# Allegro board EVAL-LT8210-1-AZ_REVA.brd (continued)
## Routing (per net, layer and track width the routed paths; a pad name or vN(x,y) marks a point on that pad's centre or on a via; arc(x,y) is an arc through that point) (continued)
UNNAMED_3_DIOLED_I1_P: length 1.5
  TOP w0.762: RPWGD3.1 DS3.A
UNNAMED_3_IND_I87_N1:
  vias: v2(103.76,249.81) v2(103.76,248.67) v2(103.76,247.52) v2(103.76,246.38) v2(103.76,245.24) v2(103.76,244.09) v2(103.76,242.95) v2(103.76,241.81) v2(103.76,240.79) v2(103.76,239.78) v2(104.9,249.81) v2(104.9,248.67) v2(104.9,247.52) v2(106.04,249.81) v2(106.04,248.67) v2(106.04,247.52) v2(106.02,242.93) v2(107.19,248.67) v2(107.19,247.52) v2(108.33,247.52) v2(108.33,246.38) v2(108.33,245.24) v2(108.33,244.09) v2(108.33,242.95) v2(108.33,241.81) v2(108.33,240.79) v2(108.33,239.78) v2(111.76,249.81) v2(111.76,248.67) v2(111.76,247.52) v2(111.76,246.38) v2(111.76,245.24) v2(111.76,244.09) v2(112.9,249.81) v2(112.9,248.67) v2(112.9,247.52) v2(112.9,246.38) v2(112.9,245.24) v2(112.9,244.09) v2(114.05,249.81) v2(114.05,248.67) v2(114.05,247.52) v2(114.05,246.38) v2(114.05,245.24) v2(114.05,244.09) v2(115.19,249.81) v2(115.19,248.67) v2(115.19,247.52) v2(115.19,246.38) v2(115.19,245.24) v2(115.19,244.09) v2(116.33,249.81) v2(116.33,248.67) v2(116.33,247.52) v2(116.33,246.38) v2(116.33,245.24) v2(116.33,244.09) v2(117.35,240.15) v2(117.47,249.81) v2(117.47,248.67) v2(117.47,247.52) v2(117.47,246.38) v2(117.47,245.24) v2(117.47,244.09) v2(118.62,249.81) v2(118.62,248.67) v2(118.62,247.52) v2(118.62,246.38) v2(118.62,245.24) v2(118.62,244.09) v2(119.76,249.81) v2(119.76,248.67) v2(119.76,247.52) v2(119.76,246.38) v2(119.76,245.24) v2(119.76,244.09) v2(120.9,249.81) v2(120.9,248.67) v2(120.9,247.52) v2(120.9,246.38) v2(120.9,245.24) v2(120.9,244.09)
UNNAMED_3_NCTESTPAD_I76_N1:
  vias: v1(118.73,211.63) v1(118.73,210.82) v1(119.46,211.63) v1(119.46,210.82) v2(70.03,252.18) v2(70.03,251.37) v2(83.03,252.18) v2(83.03,251.37)
UNNAMED_3_NCTESTPAD_I88_N1:
  vias: v1(120.5,211.63) v1(120.5,210.82) v1(121.25,211.63) v1(121.25,210.82) v2(144.58,251.97) v2(144.58,251.21) v2(157.42,252.01) v2(157.42,251.24)
UNNAMED_3_RES_I33_N2: length 96.6
  TOP w0.279: RSNS9.3 v2(58.6,222.07) ; RSNPA3.2 v2(127.46,202.86)
  L3_SIG w0.254: v2(127.46,202.86) 128.12,202.21 128.12,197.8 121.11,190.79 84.81,190.79 60.12,215.48 60.12,215.77 60.1,215.8 60.1,220.57 v2(58.6,222.07)
UNNAMED_3_RES_I37_N2: length 89.8
  TOP w0.279: RSNPB3.2 v2(127.46,198.22) ; RSNS9.1 v2(62.1,222.07)
  L3_SIG w0.254: v2(62.1,222.07) 60.58,220.55 60.58,215.67 85,191.25 120.48,191.25 127.03,197.8 127.05,197.8 v2(127.46,198.22)
UNNAMED_3_RES_I78_N1: length 30.6
  TOP w0.279: R23.1 v1(106.68,213.24) ; RSNS7.3 v1(100.48,237.97)
  L3_SIG w0.203: v1(100.48,237.97) 102.08,236.37 102.08,219.61 107.29,214.41 107.29,213.85 v1(106.68,213.24)
UNNAMED_3_RES_I84_N1: length 30.6
  TOP w0.279: RSNS7.1 v1(104.09,237.97) ; R24.1 v1(108.33,213.24)
  L3_SIG w0.203: v1(108.33,213.24) 107.7,213.88 107.7,214.57 102.49,219.78 102.49,236.37 v1(104.09,237.97)
UNNAMED_3_RES_I117_N1: length 9.1
  TOP w0.279: R1C3.1 v1(122.63,188.98) R1A3.1
  TOP w0.305: v1(127.25,192.28) R59.1
  L3_SIG w0.305: v1(127.25,192.28) 127.25,191.52 126.11,190.37 123.32,190.37 122.63,189.69 v1(122.63,188.98)
UNNAMED_3_RES_I120_N1: length 8.3
  TOP w0.279: R2A3.1 v1(121.08,188.98) R2C3.1
  TOP w0.305: v1(125.73,192.15) R60.1
  L3_SIG w0.305: v1(125.73,192.15) 124.59,191.01 122.81,191.01 121.08,189.28 v1(121.08,188.98)
UNNAMED_4_ADLT82101_I10_BG1: length 7.3
  TOP w0.279: U4.23 115.43,294.54 116.37,295.48 117.83,295.48 119.23,296.87 RBG7.2
UNNAMED_4_ADLT82101_I10_BG2: length 7.2
  TOP w0.279: RBG8.2 120.74,297.17 117.68,294.11 116.79,294.11 116.43,293.75 U4.21
UNNAMED_4_ADLT82101_I10_BST1: length 6.6
  TOP w0.279: RBST7.2 111.43,297.36 111.71,297.08 113.16,297.08 113.43,296.8 U4.27
UNNAMED_4_ADLT82101_I10_BST2: length 7.9
  TOP w0.279: U4.20 117.46,292.56 122.25,297.34 RBST8.2
UNNAMED_4_ADLT82101_I10_DG: length 93.9
  TOP w0.279: U4.34 110.27,291.06 v1(109.19,292.14)
  TOP w0.635: R31.2 30.67,310.13 v2(29.87,309.33) DG4.1
  L5_VCC w0.508: v1(109.19,292.14) 97.85,303.48 35.73,303.48 v2(29.87,309.33)
UNNAMED_4_ADLT82101_I10_FB1: length 12.1
  TOP w0.279: U4.11 117.07,286.12 119.13,284.06 121.37,284.06 122.72,282.72 R3C4.1 122.72,281.25 R1A4.2 R1B4.1
UNNAMED_4_ADLT82101_I10_FB2: length 10.5
  TOP w0.279: U4.10 116.43,286.03 118.9,283.57 120.18,283.57 121.02,282.73 R3C4.2 121.08,282.6 R2A4.2 R2B4.2
UNNAMED_4_ADLT82101_I10_GATEVCC: length 34.5
  TOP w0.279: CGATE4.1 116.81,297.63 v2(116.81,296.99) 114.93,295.11 U4.24 ; 123,304.35 DBST8.A
  TOP w0.635: v1(110.68,305.39) DBST7.A ; v2(123,305.45) 123,304.35
  L3_SIG w0.61: v2(123,305.45) 123,299.37 120.63,296.99 v2(116.81,296.99) 115.94,297.87 112.14,297.87 110.68,299.33 v1(110.68,305.39)
UNNAMED_4_ADLT82101_I10_IMON: length 15
  TOP w0.279: IMON4.1 107.38,281.14 R38.2 RIMON4.1 110.39,281.09 CIMON4.1 111.86,281.2 114.93,284.28 U4.7
UNNAMED_4_ADLT82101_I10_RT: length 9.1
  TOP w0.279: RT4.2 110.46,285.71 110.78,285.4 112.34,285.4 112.94,285.99 U4.3
UNNAMED_4_ADLT82101_I10_SNSN1: length 9.3
  TOP w0.279: U4.30 111.94,293.52 107.8,297.66 107.8,298.47 C87.2 108.33,299.08 R34.2
UNNAMED_4_ADLT82101_I10_SNSP1: length 9.8
  TOP w0.279: U4.31 111.3,293.48 107.31,297.46 107.31,298.5 C87.1 106.68,299.13 R33.2
UNNAMED_4_ADLT82101_I10_SS: length 7.8
  TOP w0.279: CSS4.2 112.43,282.57 114.43,284.58 U4.6
UNNAMED_4_ADLT82101_I10_SW1: length 45.4
  TOP w0.279: v1(109.91,297.32) 110.63,296.6 112.76,296.6 112.94,296.42 U4.28
  TOP w0.61: v1(109.91,297.32) CBST7.1
  L3_SIG w0.61: v1(109.91,297.32) 96.27,310.96 v2(96.27,329.56)
  vias: v2(69.89,334.9) v2(69.89,333.88) v2(69.89,332.87) v2(69.89,331.85) v2(70.88,339.72) v2(70.88,338.45) v2(70.88,337.18) v2(70.88,335.91) v2(71.03,334.9) v2(71.03,333.88) v2(71.03,332.87) v2(71.03,331.85) v2(71.51,339.09) v2(71.51,337.82) v2(71.51,336.55) v2(72.15,339.72) v2(72.15,338.45) v2(72.15,337.18) v2(72.15,335.91) v2(72.17,334.9) v2(72.17,333.88) v2(72.17,332.87) v2(72.17,331.85) v2(72.17,330.83) v2(72.78,339.09) v2(72.78,337.82) v2(72.78,336.55) v2(73.32,334.9) v2(73.32,333.88) v2(73.32,332.87) v2(73.32,331.85) v2(73.32,330.83) v2(73.42,339.72) v2(73.42,338.45) v2(73.42,337.18) v2(73.42,335.91) v2(74.05,339.09) v2(74.05,337.82) v2(74.05,336.55) v2(74.46,334.9) v2(74.46,333.88) v2(74.46,332.87) v2(74.46,331.85) v2(74.46,330.83) v2(74.69,339.72) v2(74.69,338.45) v2(74.69,337.18) v2(74.69,335.91) v2(75.56,334.9) v2(75.56,333.88) v2(75.56,332.87) v2(75.56,331.85) v2(75.56,330.83) v2(83.03,334.9) v2(83.03,333.88) v2(83.9,339.72) v2(83.9,338.45) v2(83.9,337.18) v2(83.9,335.91) v2(84.18,334.9) v2(84.18,333.88) v2(84.53,339.09) v2(84.53,337.82) v2(84.53,336.55) v2(85.17,339.72) v2(85.17,338.45) v2(85.17,337.18) v2(85.17,335.91) v2(85.32,334.9) v2(85.32,333.88) v2(85.32,332.87) v2(85.32,331.85) v2(85.32,330.83) v2(85.8,339.09) v2(85.8,337.82) v2(85.8,336.55) v2(86.44,339.72) v2(86.44,338.45) v2(86.44,337.18) v2(86.44,335.91) v2(86.46,334.9) v2(86.46,333.88) v2(86.46,332.87) v2(86.46,331.85) v2(86.46,330.83) v2(87.07,339.09) v2(87.07,337.82) v2(87.07,336.55) v2(87.6,334.9) v2(87.6,333.88) v2(87.6,332.87) v2(87.6,331.85) v2(87.6,330.83) v2(87.71,339.72) v2(87.71,338.45) v2(87.71,337.18) v2(87.71,335.91) v2(88.6,334.89) v2(88.6,333.87) v2(88.6,332.85) v2(88.6,331.84) v2(88.6,330.82) v2(96.27,339.6) v2(96.27,338.45) v2(96.27,337.31) v2(96.27,336.17) v2(96.27,335.03) v2(96.27,333.88) v2(96.27,332.74) v2(96.27,331.6) v2(96.27,330.58) v2(97.41,339.6) v2(97.41,338.45) v2(97.41,337.31) v2(98.55,339.6) v2(98.55,338.45) v2(98.55,337.31) v2(98.55,332.74) v2(99.69,339.6) v2(99.69,338.45) v2(99.69,337.31) v2(100.84,339.6) v2(100.84,338.45) v2(100.84,337.31) v2(100.84,336.17) v2(100.84,335.03) v2(100.84,333.88) v2(100.84,332.74) v2(100.84,331.6) v2(100.84,330.58) v2(100.84,329.56)
UNNAMED_4_ADLT82101_I10_SW2: length 61
  TOP w0.279: CBST8.2 117.66,292.06 U4.19
  TOP w0.61: v2(124.78,298.17) CBST8.2
  L3_SIG w0.61: v2(124.78,298.17) 124.78,317.44 140.08,332.74 v2(144.4,332.74) v2(145.54,332.74) v2(146.69,332.74) v2(147.83,332.74) v2(148.97,332.74) v2(149.95,332.74)
  vias: v2(123.95,339.6) v2(123.95,338.45) v2(123.95,337.31) v2(123.95,336.17) v2(123.95,335.03) v2(123.95,333.88) v2(125.09,339.6) v2(125.09,338.45) v2(125.09,337.31) v2(125.09,336.17) v2(125.09,335.03) v2(125.09,333.88) v2(126.24,339.6) v2(126.24,338.45) v2(126.24,337.31) v2(126.24,336.17) v2(126.24,335.03) v2(126.24,333.88) v2(127.38,339.6) v2(127.38,338.45) v2(127.38,337.31) v2(127.38,336.17) v2(127.38,335.03) v2(127.38,333.88) v2(127.5,329.94) v2(128.52,339.6) v2(128.52,338.45) v2(128.52,337.31) v2(128.52,336.17) v2(128.52,335.03) v2(128.52,333.88) v2(129.67,339.6) v2(129.67,338.45) v2(129.67,337.31) v2(129.67,336.17) v2(129.67,335.03) v2(129.67,333.88) v2(130.81,339.6) v2(130.81,338.45) v2(130.81,337.31) v2(130.81,336.17) v2(130.81,335.03) v2(130.81,333.88) v2(131.95,339.6) v2(131.95,338.45) v2(131.95,337.31) v2(131.95,336.17) v2(131.95,335.03) v2(131.95,333.88) v2(133.1,339.6) v2(133.1,338.45) v2(133.1,337.31) v2(133.1,336.17) v2(133.1,335.03) v2(133.1,333.88) v2(144.4,334.77) v2(144.4,333.76) v2(144.4,331.72) v2(145.29,339.65) v2(145.29,338.38) v2(145.29,337.11) v2(145.29,335.84) v2(145.54,334.77) v2(145.54,333.76) v2(145.54,331.72) v2(145.92,339.01) v2(145.92,337.74) v2(145.92,336.47) v2(146.56,339.65) v2(146.56,338.38) v2(146.56,337.11) v2(146.56,335.84) v2(146.69,334.77) v2(146.69,333.76) v2(146.69,331.72) v2(147.19,339.01) v2(147.19,337.74) v2(147.19,336.47) v2(147.83,339.65) v2(147.83,338.38) v2(147.83,337.11) v2(147.83,335.84) v2(147.83,334.77) v2(147.83,333.76) v2(147.83,331.72) v2(148.46,339.01) v2(148.46,337.74) v2(148.46,336.47) v2(148.97,334.77) v2(148.97,333.76) v2(148.97,331.72) v2(149.1,339.65) v2(149.1,338.38) v2(149.1,337.11) v2(149.1,335.84) v2(149.95,334.77) v2(149.95,333.76) v2(149.95,331.72) v2(157.39,334.73) v2(157.39,333.72) v2(158.27,339.65) v2(158.27,338.38) v2(158.27,337.11) v2(158.27,335.84) v2(158.39,334.77) v2(158.39,333.76) v2(158.9,339.01) v2(158.9,337.74) v2(158.9,336.47) v2(159.54,339.65) v2(159.54,338.38) v2(159.54,337.11) v2(159.54,335.84) v2(159.54,334.77) v2(159.54,333.76) v2(159.54,332.74) v2(159.54,331.72) v2(159.54,330.71) v2(160.17,339.01) v2(160.17,337.74) v2(160.17,336.47) v2(160.68,334.77) v2(160.68,333.76) v2(160.68,332.74) v2(160.68,331.72) v2(160.68,330.71) v2(160.81,339.65) v2(160.81,338.38) v2(160.81,337.11) v2(160.81,335.84) v2(161.44,339.01) v2(161.44,337.74) v2(161.44,336.47) v2(161.82,334.77) v2(161.82,333.76) v2(161.82,332.74) v2(161.82,331.72) v2(161.82,330.71) v2(162.08,339.65) v2(162.08,338.38) v2(162.08,337.11) v2(162.08,335.84) v2(162.97,334.77) v2(162.97,333.76) v2(162.97,332.74) v2(162.97,331.72) v2(162.97,330.71)
UNNAMED_4_ADLT82101_I10_TG1:
  vias: v2(70.08,330.33) v2(70.08,329.56) v2(83.09,330.4) v2(83.09,329.64) v2(112.13,295.91) v2(112.13,295.27)
UNNAMED_4_ADLT82101_I10_TG2: length 2.3
  TOP w0.279: U4.18 118.08,291.56
  TOP w0.508: 118.08,291.56 v2(119.33,291.56)
  vias: v2(119.33,292.37) v2(120.14,292.37) v2(120.14,291.56) v2(144.53,330) v2(144.53,329.23) v2(157.51,330) v2(157.51,329.23)
UNNAMED_4_ADLT82101_I10_VC1: length 10.4
  TOP w0.279: U4.8 115.43,283.16 RC12.1 114.93,282.49 RC10.2 114.2,280.43 114.2,280.25 R39.2 CP7.2
UNNAMED_4_ADLT82101_I10_VC2: length 10.4
  TOP w0.279: U4.9 115.93,283.19 RC12.2 116.46,282.49 RC11.2 117.22,280.4 117.22,280.23 R40.1 117.98,277.99 CP8.2
UNNAMED_4_ADLT82101_I10_VDD: length 13.4
  TOP w0.279: 106.72,283.92 112.92,283.92 113.94,284.94 U4.5
  TOP w0.635: 106.72,283.92 D7.A 105.69,281.9 CVDD4.2
UNNAMED_4_ADLT82101_I10_VIN: length 3.7
  TOP w0.279: U4.35 109.79,290.56
  TOP w0.61: RIN4.1 105.68,290.67 105.68,292.73
UNNAMED_4_ADLT82101_I10_VINP: length 9.3
  TOP w0.279: 110.3,292.11 110.86,291.56 U4.33
  TOP w0.61: 110.3,292.11 107.27,295.15 C78.2 105.62,295.15 R32.1
UNNAMED_4_ADLT82101_I10_VOUT: length 4.6
  TOP w0.279: U4.13 118.29,289.06
  TOP w0.635: 118.29,289.06 CFOUT4.1 ROUT4.1
UNNAMED_4_CAP_I22_N1:
  vias: v1(30.84,326.03) v1(30.86,312.93) v1(31.55,326.03) v1(31.57,312.92)
UNNAMED_4_CAP_I128_N2: length 149
  TOP w0.203: 121.71,286.03 v1(121.71,285.98)
  TOP w0.279: R36.2 v1(129.14,291.13) ; ROUT4.2 121.71,286.03 ; v2(174.9,311.84) RSNS11.3
  L3_SIG w0.203: v2(175.13,323.72) 176.4,322.45 176.4,313.33 v2(174.9,311.84) 176.5,310.24 176.5,302.56 164.47,290.53 129.74,290.53 v1(129.14,291.13)
  L3_SIG w0.508: v1(121.71,285.98) 121.71,288.59 129.69,296.57 155.03,296.57 v2(175.2,316.74)
  vias: v2(140.72,326.05) v2(140.72,315.68) v2(144.91,323.09) v2(144.91,321.94) v2(144.91,320.8) v2(145.29,327.96) v2(145.29,326.69) v2(145.29,325.42) v2(145.29,324.15) v2(145.92,327.33) v2(145.92,326.06) v2(145.92,324.79) v2(146.05,323.09) v2(146.05,321.94) v2(146.05,320.8) v2(146.56,327.96) v2(146.56,326.69) v2(146.56,325.42) v2(146.56,324.15) v2(147.07,315.68) v2(147.19,327.33) v2(147.19,326.06) v2(147.19,324.79) v2(147.19,323.09) v2(147.19,321.94) v2(147.19,320.8) v2(147.83,327.96) v2(147.83,326.69) v2(147.83,325.42) v2(147.83,324.15) v2(148.34,323.09) v2(148.34,321.94) v2(148.34,320.8) v2(148.46,327.33) v2(148.46,326.06) v2(148.46,324.79) v2(149.1,327.96) v2(149.1,326.69) v2(149.1,325.42) v2(149.1,324.15) v2(149.48,323.09) v2(149.48,321.94) v2(149.48,320.8) v2(150.62,323.09) v2(150.62,321.94) v2(150.62,320.8) v2(151.76,323.09) v2(151.76,321.94) v2(151.76,320.8) v2(152.91,323.09) v2(152.91,321.94) v2(152.91,320.8) v2(153.42,315.68) v2(153.54,325.92) v2(154.05,323.09) v2(154.05,321.94) v2(154.05,320.8) v2(155.19,323.09) v2(155.19,321.94) v2(155.19,320.8) v2(156.34,323.09) v2(156.34,321.94) v2(156.34,320.8) v2(157.48,323.09) v2(157.48,321.94) v2(157.48,320.8) v2(158.19,327.71) v2(158.27,326.54) v2(158.27,325.27) v2(158.27,324) v2(158.62,323.09) v2(158.62,321.94) v2(158.62,320.8) v2(158.9,327.18) v2(158.9,325.91) v2(158.9,324.64) v2(159.54,327.81) v2(159.54,326.54) v2(159.54,325.27) v2(159.54,324) v2(159.77,323.09) v2(159.77,321.94) v2(159.77,320.8) v2(160.17,327.18) v2(160.17,325.91) v2(160.17,324.64) v2(160.81,327.81) v2(160.81,326.54) v2(160.81,325.27) v2(160.81,324) v2(160.91,323.09) v2(160.91,321.94) v2(160.91,320.8) v2(161.44,327.18) v2(161.44,325.91) v2(161.44,324.64) v2(162.08,327.81) v2(162.08,326.54) v2(162.08,325.27) v2(162.08,324) v2(162.05,323.09) v2(162.05,321.94) v2(162.05,320.8) v2(163.88,317.53) v2(166.56,325.92) v2(169.52,321.14) v2(169.52,320) v2(169.52,318.86) v2(169.52,317.72) v2(169.52,316.57) v2(169.52,315.43) v2(169.52,314.29) v2(170.31,327.91) v2(170.31,327.15) v2(170.31,326.39) v2(170.66,321.14) v2(170.66,320) v2(170.66,318.86) v2(170.66,317.72) v2(170.66,316.57) v2(170.66,315.43) v2(170.66,314.29) v2(170.92,325.72) v2(170.92,324.57) v2(170.92,323.43) v2(170.92,322.29) v2(171.07,327.91) v2(171.07,327.15) v2(171.07,326.39) v2(171.81,327.86) v2(171.81,326.86) v2(171.81,325.72) v2(171.81,324.57) v2(171.81,323.43) v2(171.81,322.29) v2(171.81,321.14) v2(172.95,327.86) v2(172.95,326.86) v2(172.95,321.14) v2(172.97,316.78) v2(174.09,327.86) v2(174.09,326.86) v2(174.09,321.14) v2(175.13,326.14) v2(175.23,327.86) v2(175.23,326.86) v2(175.23,321.14) v2(175.23,320) v2(175.23,318.86) v2(175.89,326.14)
UNNAMED_4_CAP_I151_N2: length 1.5
  TOP w0.279: RC10.1 CC7.2
UNNAMED_4_CAP_I154_N2: length 1.5
  TOP w0.279: RC11.1 CC8.2
UNNAMED_4_CAPP_I25_N1: length 37.6
  TOP w0.279: v2(101.07,297.31) R32.2
  L3_SIG w0.203: v1(80.26,315.59) 80.26,304.44 87.4,297.31 v2(101.07,297.31)
  vias: v2(33.02,330.64) v2(33.02,329.37) v2(33.02,328.1) v2(33.02,326.83) v2(33.02,325.63) v2(33.02,324.48) v2(33.02,323.34) v2(33.02,322.2) v2(33.02,321.06) v2(33.02,319.91) v2(33.02,318.77) v2(33.02,317.5) v2(33.02,316.23) v2(33.02,314.96) v2(33.02,313.69) v2(33.66,330.01) v2(33.66,328.74) v2(33.66,327.47) v2(33.66,316.86) v2(33.66,315.59) v2(33.66,314.32) v2(34.16,325.63) v2(34.16,324.48) v2(34.16,323.34) v2(34.16,322.2) v2(34.16,321.06) v2(34.16,319.91) v2(34.16,318.77) v2(34.29,330.64) v2(34.29,329.37) v2(34.29,328.1) v2(34.29,326.83) v2(34.29,317.5) v2(34.29,316.23) v2(34.29,314.96) v2(34.29,313.69) v2(34.92,330.01) v2(34.92,328.74) v2(34.92,327.47) v2(34.92,316.86) v2(34.92,315.59) v2(34.92,314.32) v2(35.31,325.63) v2(35.31,324.48) v2(35.31,323.34) v2(35.31,322.2) v2(35.31,321.06) v2(35.31,319.91) v2(35.31,318.77) v2(35.56,330.64) v2(35.56,329.37) v2(35.56,328.1) v2(35.56,326.83) v2(35.56,317.5) v2(35.56,316.23) v2(35.56,314.96) v2(35.56,313.69) v2(36.2,330.01) v2(36.2,328.74) v2(36.2,327.47) v2(36.2,316.86) v2(36.2,315.59) v2(36.2,314.32) v2(36.45,325.63) v2(36.45,324.48) v2(36.45,323.34) v2(36.45,322.2) v2(36.45,321.06) v2(36.45,319.91) v2(36.45,318.77) v2(36.83,330.64) v2(36.83,329.37) v2(36.83,328.1) v2(36.83,326.83) v2(36.83,317.5) v2(36.83,316.23) v2(36.83,314.96) v2(36.83,313.69) v2(37.92,337.42) v2(46.96,313.45) v2(54.36,328.17) v2(54.36,327.02) v2(54.36,325.88) v2(54.36,324.74) v2(54.36,323.6) v2(54.36,322.45) v2(54.36,321.31) v2(54.36,320.17) v2(54.36,319.02) v2(54.36,317.88) v2(54.36,316.74) v2(54.36,315.59) v2(54.36,314.58) v2(54.36,313.56) v2(55.5,328.17) v2(55.5,327.02) v2(55.5,325.88) v2(55.5,324.74) v2(55.5,323.6) v2(55.5,322.45) v2(55.5,321.31) v2(55.8,337.37) v2(56.64,328.17) v2(56.64,327.02) v2(56.64,325.88) v2(56.64,324.74) v2(56.64,323.6) v2(56.64,322.45) v2(56.64,321.31) v2(56.62,316.81) v2(57.79,328.17) v2(57.79,327.02) v2(57.79,325.88) v2(57.79,324.74) v2(57.79,323.6) v2(57.79,322.45) v2(57.79,321.31) v2(58.93,328.17) v2(58.93,327.02) v2(58.93,325.88) v2(58.93,324.74) v2(58.93,323.6) v2(58.93,322.45) v2(58.93,321.31) v2(58.93,320.17) v2(58.93,319.02) v2(58.93,317.88) v2(58.93,316.74) v2(58.93,315.59) v2(58.93,314.58) v2(58.93,313.56) v2(61.85,328.17) v2(61.85,327.02) v2(61.85,325.88) v2(61.85,324.74) v2(61.85,323.6) v2(61.85,322.45) v2(61.85,321.31) v2(61.85,320.17) v2(61.85,319.02) v2(61.85,317.88) v2(61.85,316.74) v2(61.85,315.59) v2(61.85,314.58) v2(61.85,313.56) v2(62.99,328.17) v2(62.99,327.02) v2(62.99,325.88) v2(62.99,324.74) v2(62.99,323.6) v2(62.99,322.45) v2(62.99,321.31) v2(64.08,316.81) v2(64.13,324.74) v2(64.13,323.6) v2(64.13,322.45) v2(64.13,321.31) v2(65.28,324.74) v2(65.28,323.6) v2(65.28,322.45) v2(65.28,321.31) v2(66.18,326.05) v2(66.42,324.74) v2(66.42,323.6) v2(66.42,322.45) v2(66.42,321.31) v2(66.42,320.17) v2(66.42,319.02) v2(66.42,317.88) v2(66.42,316.74) v2(66.42,315.59) v2(66.42,314.58) v2(66.42,313.56) v2(70.9,328.21) v2(70.9,326.94) v2(70.9,325.67) v2(70.9,324.4) v2(70.99,323.21) v2(70.99,322.07) v2(70.99,320.93) v2(71.54,327.57) v2(71.54,326.3) v2(71.54,325.03) v2(72.17,328.21) v2(72.17,326.94) v2(72.17,325.67) v2(72.17,324.4) v2(72.14,323.21) v2(72.14,322.07) v2(72.14,320.93) v2(72.81,327.57) v2(72.81,326.3) v2(72.81,325.03) v2(73.15,317.88) v2(73.28,323.21) v2(73.28,322.07) v2(73.28,320.93) v2(73.44,328.21) v2(73.44,326.94) v2(73.44,325.67) v2(73.44,324.4) v2(74.08,327.57) v2(74.08,326.3) v2(74.08,325.03) v2(74.42,323.21) v2(74.42,322.07) v2(74.42,320.93) v2(74.71,328.21) v2(74.71,326.94) v2(74.71,325.67) v2(74.71,324.4) v2(75.56,323.21) v2(75.56,322.07) v2(75.56,320.93) v2(76.71,323.21) v2(76.71,322.07) v2(76.71,320.93) v2(77.85,323.21) v2(77.85,322.07) v2(77.85,320.93) v2(78.99,323.21) v2(78.99,322.07) v2(78.99,320.93) v2(79.3,326.05) v2(80.14,323.21) v2(80.14,322.07) v2(80.14,320.93) v2(81.28,323.21) v2(81.28,322.07) v2(81.28,320.93) v2(82.42,323.21) v2(82.42,322.07) v2(82.42,320.93) v2(83.57,323.21) v2(83.57,322.07) v2(83.57,320.93) v2(83.82,315.81) v2(83.92,328.21) v2(83.92,326.94) v2(83.92,325.67) v2(83.92,324.4) v2(84.56,327.57) v2(84.56,326.3) v2(84.56,325.03) v2(84.71,323.21) v2(84.71,322.07) v2(84.71,320.93) v2(85.19,328.21) v2(85.19,326.94) v2(85.19,325.67) v2(85.19,324.4) v2(85.83,327.57) v2(85.83,326.3) v2(85.83,325.03) v2(85.85,323.21) v2(85.85,322.07) v2(85.85,320.93) v2(86.46,328.21) v2(86.46,326.94) v2(86.46,325.67) v2(86.46,324.4) v2(86.99,323.21) v2(86.99,322.07) v2(86.99,320.93) v2(87.1,327.57) v2(87.1,326.3) v2(87.1,325.03) v2(87.73,328.21) v2(87.73,326.94) v2(87.73,325.67) v2(87.73,324.4) v2(88.14,323.21) v2(88.14,322.07) v2(88.14,320.93) v2(90.17,315.81) v2(92.3,326.05) v2(97.59,315.81) v2(103.62,315.81)
UNNAMED_4_DIOLED_I1_P: length 1.5
  TOP w0.762: RPWGD4.1 DS4.A
UNNAMED_4_IND_I87_N1:
  vias: v2(103.76,339.6) v2(103.76,338.45) v2(103.76,337.31) v2(103.76,336.17) v2(103.76,335.03) v2(103.76,333.88) v2(103.76,332.74) v2(103.76,331.6) v2(103.76,330.58) v2(103.76,329.56) v2(104.9,339.6) v2(104.9,338.45) v2(104.9,337.31) v2(106.04,339.6) v2(106.04,338.45) v2(106.04,337.31) v2(106.02,332.74) v2(107.19,338.45) v2(107.19,337.31) v2(108.33,337.31) v2(108.33,336.17) v2(108.33,335.03) v2(108.33,333.88) v2(108.33,332.74) v2(108.33,331.6) v2(108.33,330.58) v2(108.33,329.56) v2(111.76,339.6) v2(111.76,338.45) v2(111.76,337.31) v2(111.76,336.17) v2(111.76,335.03) v2(111.76,333.88) v2(112.9,339.6) v2(112.9,338.45) v2(112.9,337.31) v2(112.9,336.17) v2(112.9,335.03) v2(112.9,333.88) v2(114.05,339.6) v2(114.05,338.45) v2(114.05,337.31) v2(114.05,336.17) v2(114.05,335.03) v2(114.05,333.88) v2(115.19,339.6) v2(115.19,338.45) v2(115.19,337.31) v2(115.19,336.17) v2(115.19,335.03) v2(115.19,333.88) v2(116.33,339.6) v2(116.33,338.45) v2(116.33,337.31) v2(116.33,336.17) v2(116.33,335.03) v2(116.33,333.88) v2(117.35,329.94) v2(117.47,339.6) v2(117.47,338.45) v2(117.47,337.31) v2(117.47,336.17) v2(117.47,335.03) v2(117.47,333.88) v2(118.62,339.6) v2(118.62,338.45) v2(118.62,337.31) v2(118.62,336.17) v2(118.62,335.03) v2(118.62,333.88) v2(119.76,339.6) v2(119.76,338.45) v2(119.76,337.31) v2(119.76,336.17) v2(119.76,335.03) v2(119.76,333.88) v2(120.9,339.6) v2(120.9,338.45) v2(120.9,337.31) v2(120.9,336.17) v2(120.9,335.03) v2(120.9,333.88)
UNNAMED_4_NCTESTPAD_I76_N1:
  vias: v1(118.73,301.41) v1(118.73,300.61) v1(119.46,301.41) v1(119.46,300.61) v2(70,341.95) v2(70.02,341.16) v2(83.05,341.95) v2(83.06,341.16)
UNNAMED_4_NCTESTPAD_I88_N1:
  vias: v1(120.5,301.41) v1(120.5,300.61) v1(121.25,301.41) v1(121.25,300.61) v2(144.52,341.76) v2(144.53,340.99) v2(157.44,341.81) v2(157.44,341.05)
UNNAMED_4_RES_I33_N2: length 96.5
  TOP w0.279: RSNPA4.2 v2(127.46,292.65) ; RSNS12.3 v2(58.6,311.86)
  L3_SIG w0.254: v2(58.6,311.86) 60.1,310.36 60.1,305.59 60.12,305.56 60.12,305.27 84.79,280.61 121.11,280.61 128.12,287.62 128.12,291.99 v2(127.46,292.65)
UNNAMED_4_RES_I37_N2: length 89.8
  TOP w0.279: RSNPB4.2 v2(127.46,288.01) ; RSNS12.1 v2(62.1,311.86)
  L3_SIG w0.254: v2(127.46,288.01) 127.05,287.59 127.03,287.59 120.51,281.06 84.98,281.06 60.58,305.46 60.58,310.34 v2(62.1,311.86)
UNNAMED_4_RES_I78_N1: length 30.6
  TOP w0.279: R33.1 v1(106.68,303.03) ; RSNS10.3 v1(100.48,327.79)
  L3_SIG w0.203: v1(100.48,327.79) 102.1,326.17 102.1,309.38 107.3,304.17 107.3,303.65 v1(106.68,303.03)
UNNAMED_4_RES_I84_N1: length 30.6
  TOP w0.279: RSNS10.1 v1(104.09,327.79) ; R34.1 v1(108.33,303.03)
  L3_SIG w0.203: v1(104.09,327.79) 102.5,326.2 102.5,309.54 107.71,304.34 107.71,303.65 v1(108.33,303.03)
UNNAMED_4_RES_I117_N1: length 8.8
  TOP w0.279: R1C4.1 v1(122.63,278.76) R1A4.1
  TOP w0.305: v1(127.25,282.19) R61.1
  L3_SIG w0.305: v1(122.63,278.76) 122.63,279.35 124.59,281.31 126.36,281.31 v1(127.25,282.19)
UNNAMED_4_RES_I120_N1: length 8.7
  TOP w0.279: R2A4.1 v1(121.08,278.76) R2C4.1
  TOP w0.305: v1(125.73,282.19) R62.1
  L3_SIG w0.305: v1(125.73,282.19) 124.21,282.19 121.08,279.07 v1(121.08,278.76)
UNNAMED_5_ADLT8631_I47_BST: length 2.5
  TOP w0.305: U6.18 82.19,101.08 C104.2
UNNAMED_5_ADLT8631_I47_EN: length 5.2
  TOP w0.305: U6.3 82.19,90.23 R47.1 R46.2
UNNAMED_5_ADLT8631_I47_FB: length 5.9
  TOP w0.305: R49.2 88.9,99.48 R50.1 ; R49.2 88.69,99.69 87.5,99.69 86.75,98.94 U6.11 ; R49.2 88.82,99.66 C105.2
UNNAMED_5_ADLT8631_I47_IND: length 8
  TOP w0.305: L6.1 85.09,105.03 85.09,99.95 84.8,99.65 U6.14
UNNAMED_5_ADLT8631_I47_INTVCC: length 2.3
  TOP w0.305: C106.1 84.07,100.2 83.49,99.62 U6.16
UNNAMED_5_ADLT8631_I47_RT: length 3.7
  TOP w0.305: U6.8 85.45,91.21 86.23,90.42 R48.1
UNNAMED_5_ADLT8631_I47_SW: length 2.7
  TOP w0.305: C104.1 80.89,100.58 U6.20
UNNAMED_5_ADLT8631_I47_TR: length 3.8
  TOP w0.305: U6.10 86.75,90.71 C103.1
UNNAMED_5_ADLT8631_I47_VIN: length 9.3
  TOP w0.305: L5.2 78.02,89.24 80.52,86.74 84.15,86.74 84.45,87.05 R46.1
UNNAMED_5_ADLT8631_I47_VOUT: length 18.2
  TOP w0.305: R49.1 90.37,101.31 C105.1 92.2,101.26 R54.1 R53.1 R52.1 R51.1 ; R49.1 88.65,101.43 C108.1 90.81,103.26 C107.1 ; R49.1 87.44,101.31 86.1,99.96 U6.12
UNNAMED_5_ADLT8631_I98_BST: length 2.7
  TOP w0.381: C120.2 76.23,182.23 U7.18
UNNAMED_5_ADLT8631_I98_EN: length 4.5
  TOP w0.381: U7.3 76.23,172.87 75.56,172.21 75.56,171.36 R69.2 77,171.32 R70.1
UNNAMED_5_ADLT8631_I98_FB: length 4.9
  TOP w0.381: C121.2 84.28,180.89 R78.2 R79.1 82.62,179.59 U7.11
UNNAMED_5_ADLT8631_I98_INTVCC: length 3
  TOP w0.381: C122.1 77.53,181.25 U7.16
UNNAMED_5_ADLT8631_I98_RT: length 2.6
  TOP w0.381: U7.8 79.48,171.51 R71.1
UNNAMED_5_ADLT8631_I98_TR: length 2.7
  TOP w0.381: C118.1 80.78,171.61 U7.10
UNNAMED_5_ADLT8631_I98_VOUT: length 35.1
  TOP w0.381: R78.1 84.28,182.59 C121.1 ; R78.1 82.59,182.5 82.04,182.5 80.13,180.58 U7.12 ; R78.1 C124.1 84.8,184.11 C123.1
  TOP w0.508: C119.1 97.03,177.84 v1(97.03,178.69) 96.77,178.94 95.25,178.94 94.87,179.32 U8.4 ; C121.1 84.37,182.5 v1(85.34,182.5) ; v1(92.33,175.26) R75.1
  L3_SIG w0.508: 92.33,175.39 95.63,178.69 v1(97.03,178.69) ; 92.33,175.39 88.52,175.39 85.34,178.56 v1(85.34,182.5) ; 92.33,175.39 v1(92.33,175.26)
UNNAMED_5_ADLTC2052X_I74_: length 10.6
  TOP w0.508: R77.1 89.07,182.5 93.22,182.5 93.6,182.12 93.6,178.14 R73.2 R74.1
UNNAMED_5_ADLTC2052X_I74__1: length 4.1
  TOP w0.508: R76.1 R75.2 U8.2
UNNAMED_5_ADLTC2052X_I82_: length 3.8
  TOP w0.508: U8.13 92.33,187.2 91.97,187.56 91.42,187.56 91.06,187.2 U8.14
UNNAMED_5_ADLTC2052X_I83_: length 3.5
  TOP w0.508: 98.68,186.06 98.68,186.94 98.17,187.45 97.92,187.45 97.41,186.94 U8.9
UNNAMED_5_ADLTC2052X_I92_: length 3.5
  TOP w0.508: 98.68,180.46 98.68,181.36 98.17,181.86 97.92,181.86 97.41,181.36 U8.6
UNNAMED_5_DIOMMBZ5221_I58_N: length 9.6
  TOP w0.508: D2.3 99.57,175.11 99.57,173.74 98.81,172.97 96.01,172.97 94.3,174.69 R72.2 R73.1
UNNAMED_7_ADLT82101_I136_BG1: length 7.3
  TOP w0.279: RBG3.2 119.23,117.3 117.83,115.9 116.37,115.9 115.44,114.96 U2.23
UNNAMED_7_ADLT82101_I136_BG2: length 7.2
  TOP w0.279: U2.21 116.44,114.17 116.79,114.53 117.68,114.53 120.74,117.59 RBG4.2
UNNAMED_7_ADLT82101_I136_BST1: length 6.6
  TOP w0.279: U2.27 113.44,117.22 113.16,117.5 111.71,117.5 111.43,117.78 RBST3.2
UNNAMED_7_ADLT82101_I136_BST2: length 7.9
  TOP w0.279: U2.20 117.46,112.98 122.25,117.77 RBST4.2
UNNAMED_7_ADLT82101_I136_DG: length 93.8
  TOP w0.279: v1(109.19,112.56) 110.27,111.48 U2.34
  TOP w0.635: DG2.1 v2(29.9,129.67) 30.69,130.47 R11.2
  L5_VCC w0.508: v1(109.19,112.56) 97.91,123.84 35.72,123.84 v2(29.9,129.67)
UNNAMED_7_ADLT82101_I136_FB1: length 12.1
  TOP w0.279: U2.11 117.07,106.54 119.13,104.48 121.37,104.48 122.72,103.14 R3C2.1 122.72,101.67 R1A2.2 R1B2.1
UNNAMED_7_ADLT82101_I136_FB2: length 10.5
  TOP w0.279: R2B2.2 R2A2.2 121.08,103.02 R3C2.2 121.02,103.15 120.18,103.99 118.9,103.99 116.44,106.45 U2.10
UNNAMED_7_ADLT82101_I136_GATEVCC: length 34.4
  TOP w0.279: 123,124.77 DBST4.A ; CGATE2.1 116.81,118.05 v2(116.81,117.41) 114.94,115.53 U2.24
  TOP w0.635: v1(110.68,125.81) DBST3.A ; v2(123,125.88) 123,124.77
  L3_SIG w0.61: v2(123,125.88) 123,119.82 120.6,117.41 v2(116.81,117.41) 115.86,118.36 112.14,118.36 110.68,119.83 v1(110.68,125.81)
UNNAMED_7_ADLT82101_I136_IMON: length 15
  TOP w0.279: IMON2.1 107.38,101.56 R18.2 RIMON2.1 110.39,101.51 CIMON2.1 111.86,101.63 114.94,104.7 U2.7
UNNAMED_7_ADLT82101_I136_RT: length 9.1
  TOP w0.279: RT2.2 106,105.82 112.34,105.82 112.94,106.41 U2.3
UNNAMED_7_ADLT82101_I136_SNSN1: length 9.3
  TOP w0.279: U2.30 111.94,113.95 107.8,118.08 107.8,118.9 C39.2 108.33,119.5 R14.2
UNNAMED_7_ADLT82101_I136_SNSP1: length 9.8
  TOP w0.279: R13.2 106.68,119.56 C39.1 107.32,118.92 107.32,117.88 111.3,113.9 U2.31
UNNAMED_7_ADLT82101_I136_SS: length 7.8
  TOP w0.279: U2.6 114.44,105 113.17,103.74 112.69,103.74 111.95,103 CSS2.2
UNNAMED_7_ADLT82101_I136_SW1: length 45.4
  TOP w0.279: 109.91,117.74 110.63,117.02 112.76,117.02 112.94,116.84 U2.28
  TOP w0.61: v1(109.91,117.73) CBST3.1
  L3_SIG w0.61: v1(109.91,117.73) 96.41,131.23 96.41,131.26 96.27,131.4 v2(96.27,149.99)
  vias: v2(69.89,155.32) v2(69.89,154.3) v2(69.89,153.29) v2(69.89,152.27) v2(70.88,160.15) v2(70.88,158.88) v2(70.88,157.61) v2(70.88,156.34) v2(71.03,155.32) v2(71.03,154.3) v2(71.03,153.29) v2(71.03,152.27) v2(71.51,159.51) v2(71.51,158.24) v2(71.51,156.97) v2(72.15,160.15) v2(72.15,158.88) v2(72.15,157.61) v2(72.15,156.34) v2(72.17,155.32) v2(72.17,154.3) v2(72.17,153.29) v2(72.17,152.27) v2(72.17,151.26) v2(72.78,159.51) v2(72.78,158.24) v2(72.78,156.97) v2(73.32,155.32) v2(73.32,154.3) v2(73.32,153.29) v2(73.32,152.27) v2(73.32,151.26) v2(73.42,160.15) v2(73.42,158.88) v2(73.42,157.61) v2(73.42,156.34) v2(74.05,159.51) v2(74.05,158.24) v2(74.05,156.97) v2(74.46,155.32) v2(74.46,154.3) v2(74.46,153.29) v2(74.46,152.27) v2(74.46,151.26) v2(74.69,160.15) v2(74.69,158.88) v2(74.69,157.61) v2(74.69,156.34) v2(75.6,155.32) v2(75.6,154.3) v2(75.6,153.29) v2(75.6,152.27) v2(75.6,151.26) v2(83.03,155.32) v2(83.03,154.3) v2(83.9,160.15) v2(83.9,158.88) v2(83.9,157.61) v2(83.9,156.34) v2(84.18,155.32) v2(84.18,154.3) v2(84.53,159.51) v2(84.53,158.24) v2(84.53,156.97) v2(85.17,160.15) v2(85.17,158.88) v2(85.17,157.61) v2(85.17,156.34) v2(85.32,155.32) v2(85.32,154.3) v2(85.32,153.29) v2(85.32,152.27) v2(85.32,151.26) v2(85.8,159.51) v2(85.8,158.24) v2(85.8,156.97) v2(86.44,160.15) v2(86.44,158.88) v2(86.44,157.61) v2(86.44,156.34) v2(86.46,155.32) v2(86.46,154.3) v2(86.46,153.29) v2(86.46,152.27) v2(86.46,151.26) v2(87.07,159.51) v2(87.07,158.24) v2(87.07,156.97) v2(87.6,155.32) v2(87.6,154.3) v2(87.6,153.29) v2(87.6,152.27) v2(87.6,151.26) v2(87.71,160.15) v2(87.71,158.88) v2(87.71,157.61) v2(87.71,156.34) v2(88.6,155.31) v2(88.6,154.29) v2(88.6,153.28) v2(88.6,152.26) v2(88.6,151.24) v2(96.27,160.02) v2(96.27,158.88) v2(96.27,157.73) v2(96.27,156.59) v2(96.27,155.45) v2(96.27,154.3) v2(96.27,153.16) v2(96.27,152.02) v2(96.27,151) v2(97.41,160.02) v2(97.41,158.88) v2(97.41,157.73) v2(98.55,160.02) v2(98.55,158.88) v2(98.55,157.73) v2(98.53,153.14) v2(99.7,160.02) v2(99.7,158.88) v2(99.7,157.73) v2(100.84,160.02) v2(100.84,158.88) v2(100.84,157.73) v2(100.84,156.59) v2(100.84,155.45) v2(100.84,154.3) v2(100.84,153.16) v2(100.84,152.02) v2(100.84,151) v2(100.84,149.99)
UNNAMED_7_ADLT82101_I136_SW2: length 61
  TOP w0.279: U2.19 117.66,112.48 CBST4.2
  TOP w0.61: v2(124.78,118.59) CBST4.2
  L3_SIG w0.61: v2(149.97,153.16) v2(148.97,153.16) v2(147.83,153.16) v2(146.69,153.16) v2(145.54,153.16) v2(144.4,153.16) 140.08,153.16 124.78,137.86 v2(124.78,118.59)
  vias: v2(123.95,160.02) v2(123.95,158.88) v2(123.95,157.73) v2(123.95,156.59) v2(123.95,155.45) v2(123.95,154.3) v2(125.1,160.02) v2(125.1,158.88) v2(125.1,157.73) v2(125.1,156.59) v2(125.1,155.45) v2(125.1,154.3) v2(126.24,160.02) v2(126.24,158.88) v2(126.24,157.73) v2(126.24,156.59) v2(126.24,155.45) v2(126.24,154.3) v2(127.38,160.02) v2(127.38,158.88) v2(127.38,157.73) v2(127.38,156.59) v2(127.38,155.45) v2(127.38,154.3) v2(127.5,150.36) v2(128.52,160.02) v2(128.52,158.88) v2(128.52,157.73) v2(128.52,156.59) v2(128.52,155.45) v2(128.52,154.3) v2(129.67,160.02) v2(129.67,158.88) v2(129.67,157.73) v2(129.67,156.59) v2(129.67,155.45) v2(129.67,154.3) v2(130.81,160.02) v2(130.81,158.88) v2(130.81,157.73) v2(130.81,156.59) v2(130.81,155.45) v2(130.81,154.3) v2(131.95,160.02) v2(131.95,158.88) v2(131.95,157.73) v2(131.95,156.59) v2(131.95,155.45) v2(131.95,154.3) v2(133.1,160.02) v2(133.1,158.88) v2(133.1,157.73) v2(133.1,156.59) v2(133.1,155.45) v2(133.1,154.3) v2(144.4,155.19) v2(144.4,154.18) v2(144.4,152.15) v2(145.29,160.07) v2(145.29,158.8) v2(145.29,157.53) v2(145.29,156.26) v2(145.54,155.19) v2(145.54,154.18) v2(145.54,152.15) v2(145.92,159.44) v2(145.92,158.17) v2(145.92,156.9) v2(146.56,160.07) v2(146.56,158.8) v2(146.56,157.53) v2(146.56,156.26) v2(146.69,155.19) v2(146.69,154.18) v2(146.69,152.15) v2(147.19,159.44) v2(147.19,158.17) v2(147.19,156.9) v2(147.83,160.07) v2(147.83,158.8) v2(147.83,157.53) v2(147.83,156.26) v2(147.83,155.19) v2(147.83,154.18) v2(147.83,152.15) v2(148.46,159.44) v2(148.46,158.17) v2(148.46,156.9) v2(148.97,155.19) v2(148.97,154.18) v2(148.97,152.15) v2(149.1,160.07) v2(149.1,158.8) v2(149.1,157.53) v2(149.1,156.26) v2(149.97,155.19) v2(149.97,154.18) v2(149.97,152.15) v2(157.42,155.16) v2(157.42,154.14) v2(158.29,160.07) v2(158.29,158.8) v2(158.29,157.53) v2(158.29,156.26) v2(158.42,155.19) v2(158.42,154.18) v2(158.93,159.44) v2(158.93,158.17) v2(158.93,156.9) v2(159.56,160.07) v2(159.56,158.8) v2(159.56,157.53) v2(159.56,156.26) v2(159.56,155.19) v2(159.56,154.18) v2(159.56,153.16) v2(159.56,152.15) v2(159.56,151.13) v2(160.2,159.44) v2(160.2,158.17) v2(160.2,156.9) v2(160.71,155.19) v2(160.71,154.18) v2(160.71,153.16) v2(160.71,152.15) v2(160.71,151.13) v2(160.83,160.07) v2(160.83,158.8) v2(160.83,157.53) v2(160.83,156.26) v2(161.47,159.44) v2(161.47,158.17) v2(161.47,156.9) v2(161.85,155.19) v2(161.85,154.18) v2(161.85,153.16) v2(161.85,152.15) v2(161.85,151.13) v2(162.1,160.07) v2(162.1,158.8) v2(162.1,157.53) v2(162.1,156.26) v2(162.99,155.19) v2(162.99,154.18) v2(162.99,153.16) v2(162.99,152.15) v2(162.99,151.13)
UNNAMED_7_ADLT82101_I136_TG1:
  vias: v2(70.08,150.82) v2(70.08,150.06) v2(83.09,150.81) v2(83.09,150.05) v2(112.13,116.33) v2(112.13,115.7)
UNNAMED_7_ADLT82101_I136_TG2: length 2.3
  TOP w0.279: U2.18 118.08,111.98
  TOP w0.508: 118.08,111.98 v2(119.33,111.98)
  vias: v2(119.33,112.79) v2(120.14,112.79) v2(120.14,111.98) v2(144.53,150.62) v2(144.53,149.86) v2(157.53,150.62) v2(157.53,149.86)
UNNAMED_7_ADLT82101_I136_VC1: length 10.4
  TOP w0.279: CP3.2 R19.2 114.2,100.67 114.2,100.85 RC4.2 114.94,102.91 RC6.1 115.44,103.58 U2.8
UNNAMED_7_ADLT82101_I136_VC2: length 10.4
  TOP w0.279: CP4.2 117.98,98.41 R20.1 117.22,100.65 117.22,100.82 RC5.2 116.46,102.91 RC6.2 115.94,103.61 U2.9
UNNAMED_7_ADLT82101_I136_VDD: length 13.4
  TOP w0.279: U2.5 113.94,105.36 112.92,104.34 106.72,104.34
  TOP w0.635: CVDD2.2 105.69,102.32 D3.A 106.72,104.34
UNNAMED_7_ADLT82101_I136_VIN: length 3.7
  TOP w0.279: U2.35 109.79,110.98
  TOP w0.61: RIN2.1 105.68,111.1 105.68,113.16
UNNAMED_7_ADLT82101_I136_VINP: length 9.3
  TOP w0.279: 110.3,112.54 110.86,111.98 U2.33
  TOP w0.61: 110.3,112.54 107.27,115.57 C30.2 105.62,115.57 R12.1
UNNAMED_7_ADLT82101_I136_VOUT: length 4.6
  TOP w0.279: U2.13 118.29,109.48
  TOP w0.635: ROUT2.1 CFOUT2.1 118.29,109.48
UNNAMED_7_CAP_I21_N1:
  vias: v1(30.79,145.87) v1(30.86,133.35) v1(31.5,145.87) v1(31.57,133.34)
UNNAMED_7_CAP_I127_N2: length 149.1
  TOP w0.203: 147.83,144.52 147.83,144.35 v2(147.81,144.34)
  TOP w0.279: ROUT2.2 v1(121.71,106.4) ; R16.2 v1(129.14,111.55) ; v2(174.9,132.26) RSNS5.3
  L3_SIG w0.203: v1(129.14,111.55) 129.74,110.95 164.47,110.95 176.5,122.99 176.5,130.66 v2(174.9,132.26) 174.93,132.26 176.4,133.73 176.4,143 v2(175.13,144.27)
  L3_SIG w0.508: v1(121.71,106.4) 121.71,109.05 129.6,116.93 154.78,116.93 v2(174.96,137.11)
  vias: v2(140.72,146.47) v2(140.72,136.1) v2(144.91,143.34) v2(144.91,142.2) v2(144.91,141.06) v2(145.29,148.22) v2(145.29,146.95) v2(145.29,145.68) v2(145.28,144.32) v2(145.92,147.59) v2(145.92,146.32) v2(145.92,145.05) v2(146.05,143.34) v2(146.05,142.2) v2(146.05,141.06) v2(146.56,148.22) v2(146.56,146.95) v2(146.56,145.68) v2(146.55,144.35) v2(147.07,136.1) v2(147.19,147.59) v2(147.19,146.32) v2(147.19,145.05) v2(147.19,143.34) v2(147.19,142.2) v2(147.19,141.06) v2(147.83,148.22) v2(147.83,146.95) v2(147.83,145.68) v2(148.34,143.34) v2(148.34,142.2) v2(148.34,141.06) v2(148.46,147.59) v2(148.46,146.32) v2(148.46,145.05) v2(149.1,148.22) v2(149.1,146.95) v2(149.1,145.68) v2(149.09,144.35) v2(149.48,143.34) v2(149.48,142.2) v2(149.48,141.06) v2(150.62,143.34) v2(150.62,142.2) v2(150.62,141.06) v2(151.77,143.34) v2(151.77,142.2) v2(151.77,141.06) v2(152.91,143.34) v2(152.91,142.2) v2(152.91,141.06) v2(153.42,136.1) v2(153.7,146.34) v2(154.05,143.34) v2(154.05,142.2) v2(154.05,141.06) v2(155.19,143.34) v2(155.19,142.2) v2(155.19,141.06) v2(156.34,143.34) v2(156.34,142.2) v2(156.34,141.06) v2(157.48,143.34) v2(157.48,142.2) v2(157.48,141.06) v2(158.29,148.22) v2(158.29,146.95) v2(158.29,145.68) v2(158.29,144.41) v2(158.62,143.34) v2(158.62,142.2) v2(158.62,141.06) v2(158.93,147.59) v2(158.93,146.32) v2(158.93,145.05) v2(159.56,148.22) v2(159.56,146.95) v2(159.56,145.68) v2(159.56,144.41) v2(159.77,143.34) v2(159.77,142.2) v2(159.77,141.06) v2(160.2,147.59) v2(160.2,146.32) v2(160.2,145.05) v2(160.83,148.22) v2(160.83,146.95) v2(160.83,145.68) v2(160.83,144.41) v2(160.91,143.34) v2(160.91,142.2) v2(160.91,141.06) v2(161.47,147.59) v2(161.47,146.32) v2(161.47,145.05) v2(162.05,143.34) v2(162.05,142.2) v2(162.05,141.06) v2(162.1,148.22) v2(162.1,146.95) v2(162.1,145.68) v2(162.1,144.41) v2(163.88,137.93) v2(166.71,146.34) v2(169.52,141.56) v2(169.52,140.42) v2(169.52,139.28) v2(169.52,138.14) v2(169.52,136.99) v2(169.52,135.85) v2(169.52,134.71) v2(170.31,148.34) v2(170.31,147.57) v2(170.31,146.81) v2(170.66,141.56) v2(170.66,140.42) v2(170.66,139.28) v2(170.66,138.14) v2(170.66,136.99) v2(170.66,135.85) v2(170.66,134.71) v2(170.92,146.14) v2(170.92,144.99) v2(170.92,143.85) v2(170.92,142.71) v2(171.07,148.34) v2(171.07,147.57) v2(171.07,146.81) v2(171.81,148.42) v2(171.81,147.28) v2(171.81,141.56) v2(172.06,146.14) v2(172.06,144.99) v2(172.06,143.85) v2(172.06,142.71) v2(172.95,148.42) v2(172.95,147.28) v2(172.95,141.56) v2(172.99,137.39) v2(174.09,148.42) v2(174.09,147.28) v2(174.09,141.56) v2(175.23,148.42) v2(175.23,147.28) v2(175.26,146.56) v2(175.23,141.56) v2(175.23,140.42) v2(175.23,139.28) v2(175.89,146.56)
UNNAMED_7_CAP_I151_N2: length 1.5
  TOP w0.279: RC4.1 CC3.2
UNNAMED_7_CAP_I154_N2: length 1.5
  TOP w0.279: RC5.1 CC4.2
UNNAMED_7_CAPP_I24_N1: length 37.6
  TOP w0.279: v2(101.07,117.73) R12.2
  L3_SIG w0.203: v2(101.07,117.73) 87.4,117.73 80.26,124.87 v1(80.26,136.02)
  vias: v2(33.02,150.44) v2(33.02,149.17) v2(33.02,147.9) v2(33.02,146.63) v2(33.02,144.91) v2(33.02,143.76) v2(33.02,142.62) v2(33.02,141.48) v2(33.02,140.33) v2(33.02,139.19) v2(33.02,137.92) v2(33.02,136.65) v2(33.02,135.38) v2(33.02,134.11) v2(33.66,149.81) v2(33.66,148.54) v2(33.66,147.27) v2(33.66,137.29) v2(33.66,136.02) v2(33.66,134.75) v2(34.16,144.91) v2(34.16,143.76) v2(34.16,142.62) v2(34.16,141.48) v2(34.16,140.33) v2(34.16,139.19) v2(34.29,150.44) v2(34.29,149.17) v2(34.29,147.9) v2(34.29,146.63) v2(34.29,137.92) v2(34.29,136.65) v2(34.29,135.38) v2(34.29,134.11) v2(34.93,149.81) v2(34.93,148.54) v2(34.93,147.27) v2(34.93,137.29) v2(34.93,136.02) v2(34.93,134.75) v2(35.31,144.91) v2(35.31,143.76) v2(35.31,142.62) v2(35.31,141.48) v2(35.31,140.33) v2(35.31,139.19) v2(35.56,150.44) v2(35.56,149.17) v2(35.56,147.9) v2(35.56,146.63) v2(35.56,137.92) v2(35.56,136.65) v2(35.56,135.38) v2(35.56,134.11) v2(36.2,149.81) v2(36.2,148.54) v2(36.2,147.27) v2(36.2,137.29) v2(36.2,136.02) v2(36.2,134.75) v2(36.45,144.91) v2(36.45,143.76) v2(36.45,142.62) v2(36.45,141.48) v2(36.45,140.33) v2(36.45,139.19) v2(36.83,150.44) v2(36.83,149.17) v2(36.83,147.9) v2(36.83,146.63) v2(36.83,137.92) v2(36.83,136.65) v2(36.83,135.38) v2(36.83,134.11) v2(37.92,157.22) v2(47.5,133.86) v2(54.36,148.59) v2(54.36,147.45) v2(54.36,146.3) v2(54.36,145.16) v2(54.36,144.02) v2(54.36,142.87) v2(54.36,141.73) v2(54.36,140.59) v2(54.36,139.45) v2(54.36,138.3) v2(54.36,137.16) v2(54.36,136.02) v2(54.36,135) v2(54.36,133.98) v2(55.5,148.59) v2(55.5,147.45) v2(55.5,146.3) v2(55.5,145.16) v2(55.5,144.02) v2(55.5,142.87) v2(55.5,141.73) v2(55.8,157.1) v2(56.64,148.59) v2(56.64,147.45) v2(56.64,146.3) v2(56.64,145.16) v2(56.64,144.02) v2(56.64,142.87) v2(56.64,141.73) v2(56.62,137.24) v2(57.79,148.59) v2(57.79,147.45) v2(57.79,146.3) v2(57.79,145.16) v2(57.79,144.02) v2(57.79,142.87) v2(57.79,141.73) v2(58.93,148.59) v2(58.93,147.45) v2(58.93,146.3) v2(58.93,145.16) v2(58.93,144.02) v2(58.93,142.87) v2(58.93,141.73) v2(58.93,140.59) v2(58.93,139.45) v2(58.93,138.3) v2(58.93,137.16) v2(58.93,136.02) v2(58.93,135) v2(58.93,133.98) v2(61.85,148.59) v2(61.85,147.45) v2(61.85,146.3) v2(61.85,145.16) v2(61.85,144.02) v2(61.85,142.87) v2(61.85,141.73) v2(61.85,140.59) v2(61.85,139.45) v2(61.85,138.3) v2(61.85,137.16) v2(61.85,136.02) v2(61.85,135) v2(61.85,133.98) v2(62.99,148.59) v2(62.99,147.45) v2(62.99,146.3) v2(62.99,145.16) v2(62.99,144.02) v2(62.99,142.87) v2(62.99,141.73) v2(64.08,137.24) v2(64.14,145.16) v2(64.14,144.02) v2(64.14,142.87) v2(64.14,141.73) v2(65.28,145.16) v2(65.28,144.02) v2(65.28,142.87) v2(65.28,141.73) v2(66.04,145.16) v2(66.04,144.02) v2(66.04,142.87) v2(66.04,141.73) v2(66.04,140.59) v2(66.04,139.45) v2(66.04,138.3) v2(66.04,137.16) v2(66.04,136.02) v2(66.04,135) v2(66.04,133.98) v2(66.18,146.47) v2(70.9,148.58) v2(70.9,147.31) v2(70.9,146.04) v2(70.9,144.77) v2(70.99,143.64) v2(70.99,142.49) v2(70.99,141.35) v2(71.54,147.94) v2(71.54,146.67) v2(71.54,145.4) v2(72.17,148.58) v2(72.17,147.31) v2(72.17,146.04) v2(72.17,144.77) v2(72.14,143.64) v2(72.14,142.49) v2(72.14,141.35) v2(72.81,147.94) v2(72.81,146.67) v2(72.81,145.4) v2(73.15,138.31) v2(73.28,143.64) v2(73.28,142.49) v2(73.28,141.35) v2(73.44,148.58) v2(73.44,147.31) v2(73.44,146.04) v2(73.44,144.77) v2(74.08,147.94) v2(74.08,146.67) v2(74.08,145.4) v2(74.42,143.64) v2(74.42,142.49) v2(74.42,141.35) v2(74.71,148.58) v2(74.71,147.31) v2(74.71,146.04) v2(74.71,144.77) v2(75.57,143.64) v2(75.57,142.49) v2(75.57,141.35) v2(76.71,143.64) v2(76.71,142.49) v2(76.71,141.35) v2(77.85,143.64) v2(77.85,142.49) v2(77.85,141.35) v2(78.99,143.64) v2(78.99,142.49) v2(78.99,141.35) v2(79.32,146.47) v2(80.14,143.64) v2(80.14,142.49) v2(80.14,141.35) v2(81.28,143.64) v2(81.28,142.49) v2(81.28,141.35) v2(82.42,143.64) v2(82.42,142.49) v2(82.42,141.35) v2(83.57,143.64) v2(83.57,142.49) v2(83.57,141.35) v2(83.82,136.23) v2(83.92,148.63) v2(83.92,147.36) v2(83.92,146.09) v2(83.92,144.82) v2(84.56,147.99) v2(84.56,146.72) v2(84.56,145.45) v2(84.71,143.64) v2(84.71,142.49) v2(84.71,141.35) v2(85.19,148.63) v2(85.19,147.36) v2(85.19,146.09) v2(85.19,144.82) v2(85.83,147.99) v2(85.83,146.72) v2(85.83,145.45) v2(85.85,143.64) v2(85.85,142.49) v2(85.85,141.35) v2(86.46,148.63) v2(86.46,147.36) v2(86.46,146.09) v2(86.46,144.82) v2(87,143.64) v2(87,142.49) v2(87,141.35) v2(87.1,147.99) v2(87.1,146.72) v2(87.1,145.45) v2(87.73,148.63) v2(87.73,147.36) v2(87.73,146.09) v2(87.73,144.82) v2(88.14,143.64) v2(88.14,142.49) v2(88.14,141.35) v2(90.17,136.23) v2(92.3,146.47) v2(97.54,136.23) v2(103.76,136.23)
UNNAMED_7_DIOLED_I1_P: length 1.5
  TOP w0.762: RPWGD2.1 DS2.A
UNNAMED_7_IND_I86_N1:
  vias: v2(103.76,160.02) v2(103.76,158.88) v2(103.76,157.73) v2(103.76,156.59) v2(103.76,155.45) v2(103.76,154.3) v2(103.76,153.16) v2(103.76,152.02) v2(103.76,151) v2(103.76,149.99) v2(104.9,160.02) v2(104.9,158.88) v2(104.9,157.73) v2(105.99,153.14) v2(106.05,160.02) v2(106.05,158.88) v2(106.05,157.73) v2(107.19,158.88) v2(107.19,157.73) v2(108.33,157.73) v2(108.33,156.59) v2(108.33,155.45) v2(108.33,154.3) v2(108.33,153.16) v2(108.33,152.02) v2(108.33,151) v2(108.33,149.99) v2(111.76,160.02) v2(111.76,158.88) v2(111.76,157.73) v2(111.76,156.59) v2(111.76,155.45) v2(111.76,154.3) v2(112.9,160.02) v2(112.9,158.88) v2(112.9,157.73) v2(112.9,156.59) v2(112.9,155.45) v2(112.9,154.3) v2(114.05,160.02) v2(114.05,158.88) v2(114.05,157.73) v2(114.05,156.59) v2(114.05,155.45) v2(114.05,154.3) v2(115.19,160.02) v2(115.19,158.88) v2(115.19,157.73) v2(115.19,156.59) v2(115.19,155.45) v2(115.19,154.3) v2(116.33,160.02) v2(116.33,158.88) v2(116.33,157.73) v2(116.33,156.59) v2(116.33,155.45) v2(116.33,154.3) v2(117.35,150.36) v2(117.48,160.02) v2(117.48,158.88) v2(117.48,157.73) v2(117.48,156.59) v2(117.48,155.45) v2(117.48,154.3) v2(118.62,160.02) v2(118.62,158.88) v2(118.62,157.73) v2(118.62,156.59) v2(118.62,155.45) v2(118.62,154.3) v2(119.76,160.02) v2(119.76,158.88) v2(119.76,157.73) v2(119.76,156.59) v2(119.76,155.45) v2(119.76,154.3) v2(120.9,160.02) v2(120.9,158.88) v2(120.9,157.73) v2(120.9,156.59) v2(120.9,155.45) v2(120.9,154.3)
UNNAMED_7_NCTESTPAD_I75_N1:
  vias: v1(118.73,121.84) v1(118.73,121.03) v1(119.46,121.84) v1(119.46,121.03) v2(70.02,162.39) v2(70.02,161.58) v2(83.04,162.39) v2(83.04,161.58)
UNNAMED_7_NCTESTPAD_I87_N1:
  vias: v1(120.5,121.84) v1(120.5,121.03) v1(121.25,121.84) v1(121.25,121.03) v2(144.58,162.19) v2(144.58,161.43) v2(157.57,162.23) v2(157.57,161.47)
UNNAMED_7_RES_I32_N2: length 95.9
  TOP w0.279: RSNS6.3 v2(58.6,132.28) ; RSNPA2.2 v2(127.46,113.08)
  L3_SIG w0.254: v2(58.6,132.28) 60.1,130.78 60.1,126.97 86.09,100.98 121.08,100.98 128.12,108.01 128.12,112.42 v2(127.46,113.08)
UNNAMED_7_RES_I36_N2: length 89
  TOP w0.279: RSNS6.1 v2(62.1,132.28) ; RSNPB2.2 v2(127.46,108.43)
  L3_SIG w0.254: v2(127.46,108.43) 127.05,108.01 127.03,108.01 120.45,101.43 86.4,101.43 60.58,127.25 60.58,130.76 v2(62.1,132.28)
UNNAMED_7_RES_I77_N1: length 30.6
  TOP w0.279: RSNS4.3 v1(100.46,148.18) ; R13.1 v1(106.68,123.45)
  L3_SIG w0.203: v1(106.68,123.45) 107.28,124.05 107.28,124.87 102.06,130.09 102.06,146.58 v1(100.46,148.18)
UNNAMED_7_RES_I83_N1: length 30.6
  TOP w0.279: RSNS4.1 v1(104.06,148.18) ; R14.1 v1(108.33,123.45)
  L3_SIG w0.203: v1(104.06,148.18) 102.46,146.58 102.46,130.26 107.72,125 107.72,124.06 v1(108.33,123.45)
UNNAMED_7_RES_I116_N1: length 8.4
  TOP w0.279: R1A2.1 v1(122.63,99.31) R1C2.1
  TOP w0.305: v1(127.38,102.49) R63.1
  L3_SIG w0.305: v1(127.38,102.49) 126.49,101.6 124.84,101.6 122.63,99.39 v1(122.63,99.31)
UNNAMED_7_RES_I119_N1: length 8.5
  TOP w0.279: R2C2.1 v1(121.08,99.31) R2A2.1
  TOP w0.305: v1(125.73,102.49) R64.1
  L3_SIG w0.305: v1(125.73,102.49) 123.82,102.49 121.08,99.75 v1(121.08,99.31)
VC1: length 572.8
  TOP w0.279: v1(113.74,15.27) 113.41,14.94 R9.1 ; R29.1 113.41,191.97 v1(113.74,192.3) ; R39.1 113.41,281.76 v1(113.74,282.09) ; v1(113.74,102.52) 113.41,102.18 R19.1
  L3_SIG w0.279: v1(40.78,277.89) 40.79,277.88 v1(40.79,188.09) 40.79,98.34 v1(40.77,98.31) 40.79,98.29 40.79,13.79 v1(48.9,5.69)
  L5_VCC w0.279: v1(113.74,102.52) 113.15,101.93 105.6,101.93 102.99,99.32 ; v1(113.74,282.09) 113.15,281.51 105.6,281.51 101.98,277.89 v1(40.78,277.89) ; v1(40.79,188.09) 40.81,188.1 101.98,188.1 105.6,191.72 113.15,191.72 v1(113.74,192.3) ; v1(113.74,15.27) 113.19,14.72 105.24,14.72 96.22,5.69 v1(48.9,5.69) ; 61.21,98.31 v1(40.77,98.31)
  L5_VCC w0.305: 102.99,99.32 62.22,99.32 61.21,98.31
VC2: length 596.7
  TOP w0.279: v1(117.7,102.52) 117.98,102.24 R20.2 ; v1(117.7,192.3) 117.98,192.02 R30.2 ; R40.2 117.98,281.81 v1(117.7,282.09) ; v1(117.7,15.27) 117.98,14.99 R10.2
  L3_SIG w0.279: v1(39.13,276.57) 39.13,186.81 v1(39.13,186.8) 39.13,186.8 v1(39.13,97.02) 39.12,97.01 39.12,13.46 v1(48.16,4.42)
  L5_VCC w0.279: 107.54,98.2 110.31,100.97 116.15,100.97 v1(117.7,102.52) ; v1(39.13,97.02) 62.74,97.02 ; v1(117.7,15.27) 116.12,13.68 110.27,13.68 101.02,4.42 v1(48.16,4.42) ; v1(39.13,276.57) 39.14,276.57 106.34,276.57 110.31,280.54 116.15,280.54 v1(117.7,282.09) ; v1(117.7,192.3) 116.15,190.75 110.31,190.75 106.36,186.8 96.41,186.8 v1(39.13,186.8)
  L5_VCC w0.305: 62.74,97.02 63.74,97.02 64.9,98.17 107.52,98.17 107.54,98.2
VOUT: length 946.6
  TOP w0.279: R7.2 127.24,22.7 127.26,22.71 v1(129.14,22.71) ; v2(178.51,311.85) 180.3,311.85 180.31,311.84 RSNS11.1 ; v2(178.51,132.26) RSNS5.1 ; R27.2 v1(129.14,199.74) ; v2(178.51,45.02) RSNS2.1 ; R37.2 v1(129.14,289.53) ; R17.2 v1(129.14,109.95) ; v2(178.51,222.05) RSNS8.1
  TOP w0.305: 191.52,134.49 191.52,134.37
  TOP w0.61: R35.1 v2(112.95,300.68) ; R1C3.2 v2(122.63,185.48) ; R2C4.2 v2(121.08,275.27) ; R1C4.2 v2(122.63,275.27) ; R2C1.2 v2(121.08,8.45) ; R1C2.2 v2(122.63,95.7) ; R5.1 v2(112.95,33.86) ; R25.1 v2(112.95,210.89) ; R2C2.2 v2(121.08,95.7) ; R15.1 v2(112.95,121.1) ; R2C3.2 v2(121.08,185.48) ; R1C1.2 v2(122.63,8.45)
  L3_SIG w0.203: v2(178.18,323.72) 176.91,322.45 176.91,313.45 v2(178.51,311.85) 176.91,310.25 176.91,302.4 164.63,290.12 129.73,290.12 v1(129.14,289.53) ; v1(129.14,22.71) 129.71,23.29 164.28,23.29 176.92,35.94 176.92,43.43 v2(178.51,45.02) 176.97,46.56 176.97,55.69 v2(178.31,57.02) ; v2(178.18,144.27) 176.91,143 176.91,133.86 v2(178.51,132.26) 176.91,130.66 176.91,122.82 164.63,110.54 129.73,110.54 v1(129.14,109.95) ; v1(129.14,199.74) 129.73,200.33 164.63,200.33 176.91,212.61 176.91,220.45 v2(178.51,222.05) 176.91,223.65 176.91,232.54 v2(178.18,233.81)
  L5_VCC w0.508: v2(178.17,226.87) 177.23,226.87 175.89,225.54 175.89,220.9 169.11,214.12 116.18,214.12 v2(112.95,210.89) ; v2(178.17,137.08) 177.72,137.08 176.72,136.08 176.72,128.08 144.34,95.7 v2(122.63,95.7) v2(121.08,95.7) ; v2(121.08,8.45) v2(122.63,8.45) 143.07,8.45 176.59,41.97 176.59,47.88 177.61,48.89 v2(178.17,48.89) ; v2(178.17,225.73) 177.6,225.73 176.62,224.75 176.62,218.76 149.5,191.64 129.92,191.64 127.13,188.85 127.13,187.45 125.16,185.48 v2(122.63,185.48) v2(121.08,185.48) ; v2(178.17,315.52) 177.6,315.52 176.6,314.52 176.6,308.88 142.99,275.27 v2(122.63,275.27) v2(121.08,275.27) ; v2(112.95,33.86) 116.18,37.08 169.04,37.08 175.88,43.93 175.88,48.69 177.23,50.04 v2(178.17,50.04) ; v2(112.95,300.68) 116.18,303.91 168.88,303.91 175.89,310.92 175.89,315.34 177.22,316.66 v2(178.17,316.66)
  L5_VCC w0.61: v2(112.95,121.1) 116.16,124.31 169.17,124.31 175.95,131.09 175.95,136.7 177.47,138.23 v2(178.17,138.23)
  vias: v2(177.42,328.3) v2(177.42,327.53) v2(177.42,326.77) v2(177.42,326.01) v2(177.42,238.38) v2(177.42,237.62) v2(177.42,236.86) v2(177.42,236.09) v2(177.42,148.84) v2(177.42,148.08) v2(177.42,147.32) v2(177.42,146.56) v2(177.42,61.47) v2(177.42,60.83) v2(177.42,60.2) v2(177.42,59.56) v2(178.18,328.3) v2(178.18,327.53) v2(178.18,326.77) v2(178.18,326.01) v2(178.17,321.23) v2(178.17,320.09) v2(178.17,318.95) v2(178.17,317.8) v2(178.17,314.38) v2(178.17,231.44) v2(178.17,230.3) v2(178.17,229.16) v2(178.17,228.02) v2(178.17,224.59) v2(178.18,148.84) v2(178.18,148.08) v2(178.17,147.37) v2(178.18,146.56) v2(178.17,141.66) v2(178.17,140.51) v2(178.17,139.37) v2(178.17,135.94) v2(178.17,134.8) v2(178.17,61.47) v2(178.18,60.83) v2(178.18,60.2) v2(178.18,59.56) v2(178.17,54.61) v2(178.17,53.47) v2(178.17,52.32) v2(178.17,51.18) v2(178.17,47.88) v2(178.17,46.86) v2(178.44,238.38) v2(178.44,237.62) v2(178.44,236.86) v2(178.44,236.09) v2(178.8,335.9) v2(178.8,332.47) v2(178.82,246.11) v2(178.82,242.68) v2(178.82,156.32) v2(178.82,152.9) v2(178.82,69.25) v2(178.82,65.82) v2(179.31,327.95) v2(179.31,326.95) v2(179.32,326.14) v2(179.31,321.23) v2(179.32,238.38) v2(179.32,237.62) v2(179.32,236.86) v2(179.32,236.09) v2(179.31,231.44) v2(179.31,148.51) v2(179.31,147.37) v2(179.32,146.69) v2(179.31,141.66) v2(179.32,61.47) v2(179.32,60.83) v2(179.32,60.2) v2(179.32,59.56) v2(179.31,54.61) v2(179.94,335.9) v2(179.94,332.47) v2(179.96,246.11) v2(179.96,242.68) v2(179.96,156.32) v2(179.96,152.9) v2(179.96,69.25) v2(179.96,65.82) v2(180.25,227.07) v2(180.45,327.95) v2(180.45,326.95) v2(180.47,326.14) v2(180.45,321.23) v2(180.43,316.75) v2(180.45,238.3) v2(180.45,237.16) v2(180.45,236.14) v2(180.45,231.44) v2(180.45,148.51) v2(180.45,147.37) v2(180.47,146.69) v2(180.45,141.66) v2(180.45,137.35) v2(180.45,61.47) v2(180.45,60.32) v2(180.45,59.44) v2(180.45,54.61) v2(180.49,50.04) v2(181.08,335.9) v2(181.08,332.47) v2(181.11,246.11) v2(181.11,242.68) v2(181.11,156.32) v2(181.11,152.9) v2(181.11,69.25) v2(181.11,65.82) v2(181.22,325.81) v2(181.22,324.66) v2(181.22,323.52) v2(181.22,322.38) v2(181.22,234.87) v2(181.22,233.73) v2(181.22,232.59) v2(181.22,146.23) v2(181.22,145.08) v2(181.22,143.94) v2(181.22,142.8) v2(181.22,58.04) v2(181.22,56.9) v2(181.22,55.75) v2(181.6,327.95) v2(181.6,326.95) v2(181.6,321.23) v2(181.6,238.3) v2(181.6,237.16) v2(181.6,236.14) v2(181.6,231.44) v2(181.6,148.51) v2(181.6,147.37) v2(181.6,141.66) v2(181.6,61.47) v2(181.6,60.32) v2(181.6,59.44) v2(181.6,54.61) v2(181.69,244.42) v2(181.69,154.63) v2(181.69,67.56) v2(181.99,334.16) v2(181.98,234.87) v2(181.98,233.73) v2(181.98,232.59) v2(181.98,146.23) v2(181.98,145.08) v2(181.98,143.94) v2(181.98,142.8) v2(181.98,58.04) v2(181.98,56.9) v2(181.98,55.75) v2(182.11,325.81) v2(182.11,324.66) v2(182.11,323.52) v2(182.11,322.38) v2(182.22,335.9) v2(182.22,332.47) v2(182.25,246.11) v2(182.25,242.68) v2(182.25,156.32) v2(182.25,152.9) v2(182.25,69.25) v2(182.25,65.82) v2(182.74,327.95) v2(182.74,326.95) v2(182.74,321.23) v2(182.74,320.09) v2(182.74,318.95) v2(182.74,317.8) v2(182.74,316.66) v2(182.74,315.52) v2(182.74,314.38) v2(182.74,313.23) v2(182.74,238.3) v2(182.74,237.16) v2(182.74,236.14) v2(182.74,234.87) v2(182.74,233.73) v2(182.74,232.59) v2(182.74,231.44) v2(182.74,230.3) v2(182.74,229.16) v2(182.74,228.02) v2(182.74,226.87) v2(182.74,225.73) v2(182.74,224.59) v2(182.74,223.44) v2(182.74,148.51) v2(182.74,147.37) v2(182.74,146.23) v2(182.74,145.08) v2(182.74,143.94) v2(182.74,142.8) v2(182.74,141.66) v2(182.74,140.51) v2(182.74,139.37) v2(182.74,138.23) v2(182.74,137.08) v2(182.74,135.94) v2(182.74,134.8) v2(182.74,133.65) v2(182.74,61.47) v2(182.74,60.32) v2(182.74,59.44) v2(182.74,58.04) v2(182.74,56.9) v2(182.74,55.75) v2(182.74,54.61) v2(182.74,53.47) v2(182.74,52.32) v2(182.74,51.18) v2(182.74,50.04) v2(182.74,48.89) v2(182.74,47.88) v2(182.74,46.86) v2(182.99,325.81) v2(182.99,324.66) v2(182.99,323.52) v2(182.99,322.38) v2(183.37,335.9) v2(183.37,332.47) v2(183.39,246.11) v2(183.39,242.68) v2(183.39,156.32) v2(183.39,152.9) v2(183.39,69.25) v2(183.39,65.82) v2(183.88,327.95) v2(183.88,326.95) v2(183.88,325.81) v2(183.88,324.66) v2(183.88,323.52) v2(183.88,322.38) v2(183.88,321.23) v2(183.88,320.09) v2(183.88,318.95) v2(183.88,317.8) v2(183.88,316.66) v2(183.88,315.52) v2(183.88,314.38) v2(183.88,313.23) v2(183.88,238.3) v2(183.88,237.16) v2(183.88,236.14) v2(183.88,234.87) v2(183.88,233.73) v2(183.88,232.59) v2(183.88,231.44) v2(183.88,230.3) v2(183.88,229.16) v2(183.88,228.02) v2(183.88,226.87) v2(183.88,225.73) v2(183.88,224.59) v2(183.88,223.44) v2(183.88,148.51) v2(183.88,147.37) v2(183.88,146.23) v2(183.88,145.08) v2(183.88,143.94) v2(183.88,142.8) v2(183.88,141.66) v2(183.88,140.51) v2(183.88,139.37) v2(183.88,138.23) v2(183.88,137.08) v2(183.88,135.94) v2(183.88,134.8) v2(183.88,133.65) v2(183.88,61.47) v2(183.88,60.32) v2(183.88,59.44) v2(183.88,58.04) v2(183.88,56.9) v2(183.88,55.75) v2(183.88,54.61) v2(183.88,53.47) v2(183.88,52.32) v2(183.88,51.18) v2(183.88,50.04) v2(183.88,48.89) v2(183.88,47.88) v2(183.88,46.86) v2(185.75,273.69) v2(185.75,94.36) v2(186.18,276.13) v2(186.18,271.24) v2(186.18,96.81) v2(186.18,91.91) v2(187.43,278.29) v2(187.43,269.08) v2(187.43,98.97) v2(187.43,89.76) v2(189.33,279.89) v2(189.33,267.48) v2(189.33,100.56) v2(189.33,88.16) v2(191.67,280.74) v2(191.67,266.63) v2(191.67,101.42) v2(191.67,87.31) v2(194.16,280.74) v2(194.16,266.63) v2(194.16,101.42) v2(194.16,87.31) v2(196.49,279.89) v2(196.49,267.48) v2(196.49,100.56) v2(196.49,88.16) v2(198.4,278.29) v2(198.4,269.08) v2(198.4,98.97) v2(198.4,89.76) v2(199.64,276.13) v2(199.64,271.24) v2(199.64,96.81) v2(199.64,91.91) v2(200.08,273.69) v2(200.08,94.36)
